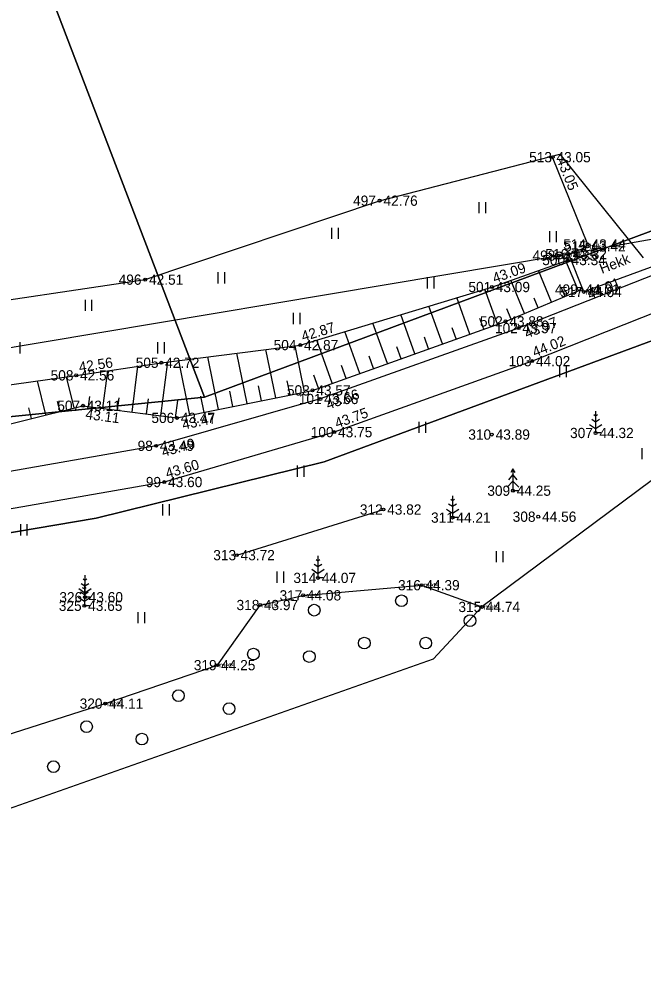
# Model space of a CAD drawing. Extents: x 505800 to 507326, y 6540058 to 6542128.
# Drawn here: x 506203.3 to 506246, y 6540215.6 to 6540280.2 of the extents above; entities that cross this region are included whole.
import ezdxf

# ---------------------------------------------------------------- set-up
doc = ezdxf.new("R2010")
doc.units = 0
for name, color, linetype in [('AED', 7, 'Continuous'), ('HALJASTUS', 7, 'Continuous'), ('KORGUS-EH2000', 7, 'Continuous'), ('MAAMUDEL', 7, 'Continuous'), ('MOOTKORG-EH2000', 7, 'Continuous'), ('MOOTMPUNKT', 7, 'Continuous'), ('MOOTNR', 7, 'Continuous'), ('MOOTPIIR', 7, 'Continuous'), ('MPOHULIIN', 7, 'Continuous'), ('PIIR', 7, 'Continuous'), ('POST', 7, 'Continuous'), ('PUU', 7, 'Continuous'), ('RELJEEF', 7, 'Continuous'), ('TEE', 7, 'Continuous')]:
    doc.layers.add(name, color=color, linetype=linetype)

msp = doc.modelspace()

# ---------------------------------------------------------------- linework, layer by layer
at = {"layer": 'AED'}
msp.add_line((506242.164, 6540264.794), (506239.766, 6540270.763), dxfattribs=at)
at = {"layer": 'HALJASTUS'}
for p, q in [((506234.721, 6540267.693), (506234.721, 6540266.931)), ((506235.176, 6540267.693), (506235.176, 6540266.931)), ((506224.632, 6540265.93), (506224.632, 6540265.169)), ((506225.087, 6540265.93), (506225.087, 6540265.169)), ((506239.555, 6540265.71), (506239.555, 6540264.948)), ((506240.011, 6540265.71), (506240.011, 6540264.948)), ((506216.865, 6540262.885), (506216.865, 6540262.124)), ((506217.32, 6540262.885), (506217.32, 6540262.124)), ((506231.188, 6540262.545), (506231.188, 6540261.784)), ((506231.643, 6540262.545), (506231.643, 6540261.784)), ((506207.776, 6540261.002), (506207.776, 6540260.241)), ((506208.231, 6540261.002), (506208.231, 6540260.241)), ((506222.019, 6540260.101), (506222.019, 6540259.34)), ((506222.474, 6540260.101), (506222.474, 6540259.34)), ((506203.307, 6540258.098), (506203.307, 6540257.337)), ((506212.731, 6540258.098), (506212.731, 6540257.337)), ((506213.186, 6540258.098), (506213.186, 6540257.337)), ((506240.227, 6540256.466), (506240.227, 6540255.705)), ((506240.682, 6540256.466), (506240.682, 6540255.705)), ((506230.618, 6540252.661), (506230.618, 6540251.9)), ((506231.073, 6540252.661), (506231.073, 6540251.9)), ((506245.872, 6540250.858), (506245.872, 6540250.097)), ((506222.291, 6540249.656), (506222.291, 6540248.895)), ((506222.746, 6540249.656), (506222.746, 6540248.895)), ((506213.082, 6540247.012), (506213.082, 6540246.251)), ((506213.537, 6540247.012), (506213.537, 6540246.251)), ((506218.159, 6540243.535), (506228.187, 6540246.655)), ((506203.353, 6540245.65), (506203.353, 6540244.889)), ((506203.808, 6540245.65), (506203.808, 6540244.889)), ((506235.903, 6540243.807), (506235.903, 6540243.046)), ((506236.358, 6540243.807), (506236.358, 6540243.046)), ((506220.889, 6540242.405), (506220.889, 6540241.644)), ((506221.344, 6540242.405), (506221.344, 6540241.644)), ((506211.401, 6540239.641), (506211.401, 6540238.88)), ((506211.856, 6540239.641), (506211.856, 6540238.88))]:
    msp.add_line(p, q, dxfattribs=at)
for points in [[(506298.533, 6540313.056), (506300.788, 6540309.079), (506301.915, 6540305.332), (506301.34, 6540302.125), (506297.996, 6540298.309), (506290.085, 6540289.615), (506283.777, 6540282.658), (506277.199, 6540276.527), (506270.683, 6540272.177), (506261.206, 6540268.283), (506249.615, 6540264.383), (506241.896, 6540261.54), (506240.872, 6540264.129), (506242.157, 6540264.661)], [(506188.596, 6540225.549), (506200.645, 6540230.665), (506209.16, 6540233.376), (506216.83, 6540236.009), (506219.751, 6540240.123), (506222.695, 6540240.784), (506230.801, 6540241.479), (506234.931, 6540239.99)]]:
    msp.add_lwpolyline(points, dxfattribs=at)
for centre in [(506229.424, 6540240.411), (506223.459, 6540239.77), (506234.109, 6540239.049), (506226.882, 6540237.517), (506231.086, 6540237.517), (506219.295, 6540236.765), (506223.118, 6540236.595), (506214.17, 6540233.921), (506217.633, 6540233.03), (506207.884, 6540231.798), (506211.668, 6540230.947), (506205.622, 6540229.064)]:
    msp.add_circle(centre, 0.4, dxfattribs=at)
at = {"layer": 'KORGUS-EH2000'}
for centre in [(506239.766, 6540270.763), (506227.932, 6540267.786), (506242.157, 6540264.661), (506242.164, 6540264.794), (506240.207, 6540264.027), (506240.802, 6540263.724), (506240.872, 6540264.129), (506211.896, 6540262.383), (506235.612, 6540261.879), (506241.741, 6540261.71), (506241.896, 6540261.54), (506236.54, 6540259.529), (506237.432, 6540259.066), (506222.499, 6540257.905), (506212.996, 6540256.696), (506238.366, 6540256.809), (506207.175, 6540255.835), (506223.339, 6540254.808), (506223.872, 6540254.219), (506207.632, 6540253.756), (506214.067, 6540252.925), (506224.827, 6540251.952), (506235.605, 6540251.785), (506242.707, 6540251.893), (506212.634, 6540251.013), (506213.198, 6540248.536), (506237.046, 6540247.944), (506228.187, 6540246.655), (506238.782, 6540246.165), (506232.919, 6540246.101), (506218.159, 6540243.535), (506223.713, 6540241.977), (506230.801, 6540241.479), (506207.77, 6540240.654), (506222.695, 6540240.784), (506207.733, 6540240.071), (506219.751, 6540240.123), (506234.931, 6540239.99), (506216.83, 6540236.009), (506209.16, 6540233.376)]:
    msp.add_circle(centre, 0.1, dxfattribs=at)
at = {"layer": 'MOOTMPUNKT'}
for centre in [(506239.766, 6540270.763), (506227.932, 6540267.786), (506242.157, 6540264.661), (506242.164, 6540264.794), (506240.207, 6540264.027), (506240.802, 6540263.724), (506240.872, 6540264.129), (506211.896, 6540262.383), (506235.612, 6540261.879), (506241.741, 6540261.71), (506241.896, 6540261.54), (506236.54, 6540259.529), (506237.432, 6540259.066), (506222.499, 6540257.905), (506212.996, 6540256.696), (506238.366, 6540256.809), (506207.175, 6540255.835), (506223.339, 6540254.808), (506223.872, 6540254.219), (506207.632, 6540253.756), (506214.067, 6540252.925), (506224.827, 6540251.952), (506235.605, 6540251.785), (506242.707, 6540251.893), (506212.634, 6540251.013), (506213.198, 6540248.536), (506237.046, 6540247.944), (506228.187, 6540246.655), (506238.782, 6540246.165), (506232.919, 6540246.101), (506218.159, 6540243.535), (506223.713, 6540241.977), (506230.801, 6540241.479), (506207.77, 6540240.654), (506222.695, 6540240.784), (506207.733, 6540240.071), (506219.751, 6540240.123), (506234.931, 6540239.99), (506216.83, 6540236.009), (506209.16, 6540233.376)]:
    msp.add_circle(centre, 0.1, dxfattribs=at)
at = {"layer": 'MOOTPIIR'}
for points in [[(506083.03, 6540240.114), (506097.119, 6540244.795), (506135.023, 6540255.311), (506160.43, 6540256.455), (506171.091, 6540256.503), (506184.044, 6540258.184), (506197.806, 6540260.288), (506211.896, 6540262.383), (506227.932, 6540267.786), (506240.253, 6540270.959), (506245.955, 6540263.864)], [(506248.469, 6540250.071), (506234.931, 6540239.99), (506231.591, 6540236.406), (506193.196, 6540222.875), (506188.596, 6540225.549), (506168.901, 6540229.957), (506140.91, 6540229.168), (506108.07, 6540216.496), (506098.399, 6540223.506), (506079.917, 6540216.55)]]:
    msp.add_lwpolyline(points, dxfattribs=at)
at = {"layer": 'MPOHULIIN'}
msp.add_lwpolyline([(506112.189, 6540233.927), (506153.828, 6540249.522), (506196.936, 6540256.778), (506240.207, 6540264.027), (506283.784, 6540271.755), (506305.802, 6540315.044)], dxfattribs=at)
at = {"layer": 'PIIR'}
for points in [[(506190.15, 6540321.81), (506202.45, 6540325.81), (506206.43, 6540327.67), (506257.9, 6540343.01), (506275.56, 6540347.96), (506281.36, 6540349.61), (506282.62, 6540347.28), (506304.35, 6540308.95), (506274.54, 6540277.85), (506268.55, 6540273.9), (506215.95, 6540254.34)], [(506133.36, 6540278.52), (506190.15, 6540321.81), (506215.95, 6540254.34), (506141.06, 6540246.81)]]:
    msp.add_lwpolyline(points, close=True, dxfattribs=at)
for points in [[(506272.39, 6540267.75), (506224.13, 6540249.92), (506208.53, 6540246.07), (506198.96, 6540244.45), (506187, 6540243.59), (506158.97, 6540240.95), (506142.88, 6540238.84), (506141.06, 6540246.81), (506215.95, 6540254.34), (506268.55, 6540273.9)], [(506028.99, 6540136.11), (506018.19, 6540200.68), (506049.36, 6540212.6), (506053.99, 6540200.79), (506052.51, 6540200.31), (506055.45, 6540190.69), (506062.61, 6540193.04), (506059.62, 6540202.68), (506057.79, 6540202.01), (506053.1, 6540214.07), (506081.75, 6540225.93), (506090.32, 6540182.64), (506150.17, 6540208.02), (506142.88, 6540238.84), (506158.97, 6540240.95), (506187, 6540243.59), (506198.96, 6540244.45), (506208.53, 6540246.07), (506224.13, 6540249.92), (506272.39, 6540267.75)]]:
    msp.add_lwpolyline(points, dxfattribs=at)
at = {"layer": 'POST'}
msp.add_circle((506240.207, 6540264.027), 0.25, dxfattribs=at)
at = {"layer": 'PUU'}
for p, q in [((506242.707, 6540253.393), (506242.707, 6540251.893)), ((506242.707, 6540252.643), (506242.44, 6540252.821)), ((506242.707, 6540253.043), (506242.582, 6540253.126)), ((506242.831, 6540253.126), (506242.707, 6540253.043)), ((506242.973, 6540252.821), (506242.707, 6540252.643)), ((506242.282, 6540252.482), (506242.707, 6540252.2)), ((506242.707, 6540252.2), (506243.131, 6540252.482)), ((506243.067, 6540251.893), (506242.707, 6540251.893)), ((506237.046, 6540249.444), (506236.896, 6540249.194)), ((506237.196, 6540249.194), (506237.046, 6540249.444)), ((506237.046, 6540249.444), (506237.046, 6540247.944)), ((506237.046, 6540249.044), (506236.746, 6540248.694)), ((506237.346, 6540248.694), (506237.046, 6540249.044)), ((506237.046, 6540248.594), (506236.646, 6540248.194)), ((506237.446, 6540248.194), (506237.046, 6540248.594)), ((506232.919, 6540247.601), (506232.919, 6540246.101)), ((506237.406, 6540247.944), (506237.046, 6540247.944)), ((506232.919, 6540246.851), (506232.652, 6540247.028)), ((506232.919, 6540247.251), (506232.794, 6540247.334)), ((506233.043, 6540247.334), (506232.919, 6540247.251)), ((506233.185, 6540247.028), (506232.919, 6540246.851)), ((506232.495, 6540246.69), (506232.919, 6540246.407)), ((506232.919, 6540246.407), (506233.343, 6540246.69)), ((506233.279, 6540246.101), (506232.919, 6540246.101)), ((506223.713, 6540243.127), (506223.589, 6540243.21)), ((506223.713, 6540243.477), (506223.713, 6540241.977)), ((506223.838, 6540243.21), (506223.713, 6540243.127)), ((506223.289, 6540242.567), (506223.713, 6540242.284)), ((506223.713, 6540242.727), (506223.447, 6540242.905)), ((506223.98, 6540242.905), (506223.713, 6540242.727)), ((506223.713, 6540242.284), (506224.138, 6540242.567)), ((506207.77, 6540241.804), (506207.646, 6540241.886)), ((506207.77, 6540242.154), (506207.77, 6540240.654)), ((506207.895, 6540241.886), (506207.77, 6540241.804)), ((506224.073, 6540241.977), (506223.713, 6540241.977)), ((506207.346, 6540241.243), (506207.77, 6540240.96)), ((506207.77, 6540241.404), (506207.504, 6540241.581)), ((506207.733, 6540241.221), (506207.609, 6540241.304)), ((506207.733, 6540241.571), (506207.733, 6540240.071)), ((506207.858, 6540241.304), (506207.733, 6540241.221)), ((506208.037, 6540241.581), (506207.77, 6540241.404)), ((506207.77, 6540240.96), (506208.194, 6540241.243)), ((506207.309, 6540240.66), (506207.733, 6540240.378)), ((506207.733, 6540240.821), (506207.467, 6540240.999)), ((506208, 6540240.999), (506207.733, 6540240.821)), ((506207.733, 6540240.378), (506208.158, 6540240.66)), ((506208.13, 6540240.654), (506207.77, 6540240.654)), ((506208.093, 6540240.071), (506207.733, 6540240.071))]:
    msp.add_line(p, q, dxfattribs=at)
at = {"layer": 'RELJEEF'}
for p, q in [((506241.536, 6540261.624), (506240.674, 6540263.679)), ((506239.691, 6540260.85), (506238.787, 6540263.008)), ((506235.991, 6540259.333), (506235.133, 6540261.734)), ((506237.847, 6540260.077), (506236.9, 6540262.337)), ((506240.614, 6540261.237), (506240.349, 6540261.869)), ((506234.108, 6540258.659), (506233.216, 6540261.153)), ((506238.769, 6540260.464), (506238.491, 6540261.126)), ((506232.225, 6540257.986), (506231.3, 6540260.572)), ((506230.342, 6540257.312), (506229.384, 6540259.991)), ((506236.925, 6540259.69), (506236.634, 6540260.384)), ((506228.458, 6540256.639), (506227.467, 6540259.411)), ((506235.05, 6540258.996), (506234.787, 6540259.73)), ((506226.575, 6540255.965), (506225.551, 6540258.83)), ((506233.166, 6540258.323), (506232.894, 6540259.085)), ((506222.787, 6540254.696), (506222.145, 6540257.86)), ((506224.692, 6540255.292), (506223.635, 6540258.249)), ((506231.283, 6540257.649), (506231.001, 6540258.439)), ((506218.867, 6540253.9), (506218.166, 6540257.353)), ((506220.827, 6540254.298), (506220.155, 6540257.607)), ((506229.4, 6540256.976), (506229.108, 6540257.793)), ((506212.974, 6540253.066), (506213.451, 6540256.754)), ((506214.947, 6540253.104), (506214.187, 6540256.847)), ((506216.907, 6540253.502), (506216.177, 6540257.1)), ((506227.517, 6540256.302), (506227.215, 6540257.148)), ((506209.007, 6540253.579), (506209.34, 6540256.155)), ((506210.991, 6540253.322), (506211.396, 6540256.459)), ((506225.634, 6540255.629), (506225.321, 6540256.502)), ((506205.095, 6540253.129), (506204.517, 6540255.465)), ((506207.037, 6540253.609), (506206.509, 6540255.742)), ((506221.807, 6540254.497), (506221.61, 6540255.468)), ((506223.751, 6540254.955), (506223.428, 6540255.856)), ((506217.887, 6540253.701), (506217.673, 6540254.759)), ((506219.847, 6540254.099), (506219.641, 6540255.113)), ((506206.066, 6540253.369), (506205.9, 6540254.039)), ((506208.016, 6540253.707), (506208.105, 6540254.396)), ((506209.999, 6540253.45), (506210.11, 6540254.307)), ((506211.983, 6540253.194), (506212.115, 6540254.219)), ((506213.966, 6540252.938), (506214.119, 6540254.122)), ((506215.927, 6540253.303), (506215.704, 6540254.404)), ((506204.125, 6540252.889), (506203.944, 6540253.62))]:
    msp.add_line(p, q, dxfattribs=at)
for points in [[(506186.229, 6540254.552), (506197.842, 6540254.535), (506207.175, 6540255.835), (506212.996, 6540256.696), (506222.499, 6540257.905), (506235.612, 6540261.879), (506240.802, 6540263.724)], [(506187.313, 6540250.618), (506199.797, 6540251.818), (506207.632, 6540253.756), (506214.067, 6540252.925), (506223.339, 6540254.808), (506236.54, 6540259.529), (506241.741, 6540261.71)]]:
    msp.add_lwpolyline(points, dxfattribs=at)
at = {"layer": 'TEE'}
for points in [[(506250.031, 6540264.042), (506237.432, 6540259.066), (506223.872, 6540254.219), (506212.634, 6540251.013), (506200.022, 6540248.8), (506187.383, 6540247.629), (506174.426, 6540246.673), (506168.123, 6540246.063), (506162.988, 6540245.422), (506156.937, 6540244.719), (506147.401, 6540244.066), (506139.254, 6540244.367), (506135.743, 6540244.402), (506126.133, 6540243.916), (506116.327, 6540241.664), (506104.313, 6540238.326), (506099.073, 6540236.742), (506091.024, 6540234.378), (506084.768, 6540232.16)], [(506250.904, 6540261.782), (506238.366, 6540256.809), (506224.827, 6540251.952), (506213.198, 6540248.536), (506200.494, 6540246.321), (506187.779, 6540245.271), (506174.602, 6540244.231), (506168.346, 6540243.484), (506163.12, 6540242.933), (506157.471, 6540242.007), (506148.214, 6540239.664), (506142.677, 6540239.46), (506137.814, 6540240.039)]]:
    msp.add_lwpolyline(points, dxfattribs=at)

# ---------------------------------------------------------------- texts
at = {"layer": 'HALJASTUS'}
msp.add_text('Hekk', height=0.7, rotation=21.06856, dxfattribs=at).set_placement((506243.135, 6540262.775))
at = {"layer": 'KORGUS-EH2000'}
for s, rotation, p in [(' 43.05', 291.88791, (506239.928, 6540270.828)), (' 43.09', 19.57223, (506235.553, 6540262.044)), (' 44.01', 22.74412, (506242.08, 6540260.903)), (' 43.97', 21.5507, (506237.753, 6540258.253)), (' 42.87', 16.86057, (506222.448, 6540258.072)), (' 44.02', 21.63789, (506238.301, 6540256.971)), (' 42.56', 8.41099, (506207.149, 6540256.008)), (' 43.66', 19.67109, (506224.166, 6540253.395)), (' 43.11', 352.63708, (506207.52, 6540252.889)), (' 43.75', 19.73504, (506224.768, 6540252.117)), (' 43.47', 11.48011, (506214.241, 6540252.067)), (' 43.49', 15.9231, (506212.874, 6540250.172)), (' 43.60', 16.37079, (506213.149, 6540248.704))]:
    msp.add_text(s, height=0.7, rotation=rotation, dxfattribs=at).set_placement(p)
for s, p in [(' 42.76', (506227.932, 6540267.436)), (' 43.42', (506242.157, 6540264.311)), (' 42.51', (506211.896, 6540262.033)), (' 43.89', (506235.605, 6540251.435)), (' 43.82', (506228.187, 6540246.305)), (' 44.56', (506238.782, 6540245.815)), (' 43.72', (506218.159, 6540243.185)), (' 44.39', (506230.801, 6540241.129)), (' 43.65', (506207.733, 6540239.721)), (' 43.97', (506219.751, 6540239.772)), (' 44.74', (506234.931, 6540239.64)), (' 44.25', (506216.83, 6540235.659)), (' 44.11', (506209.16, 6540233.026))]:
    msp.add_text(s, height=0.7, dxfattribs=at).set_placement(p)
at = {"layer": 'MAAMUDEL'}
for s, p in [(' hek', (506240.872, 6540263.954)), (' hek', (506242.157, 6540264.486)), (' hek', (506241.896, 6540261.365)), (' mets', (506230.801, 6540241.304)), (' mets', (506222.695, 6540240.609)), (' mets', (506219.751, 6540239.947)), (' mets', (506234.931, 6540239.815)), (' mets', (506216.83, 6540235.834)), (' mets', (506209.16, 6540233.201))]:
    msp.add_text(s, height=0.35, dxfattribs=at).set_placement(p)
at = {"layer": 'MOOTKORG-EH2000'}
for s, p in [(' 43.05', (506239.766, 6540270.413)), (' 42.76', (506227.932, 6540267.436)), (' 43.42', (506242.157, 6540264.311)), (' 43.44', (506242.164, 6540264.444)), (' 43.35', (506240.207, 6540263.677)), (' 43.32', (506240.872, 6540263.779)), (' 43.34', (506240.802, 6540263.374)), (' 42.51', (506211.896, 6540262.033)), (' 43.09', (506235.612, 6540261.529)), (' 44.01', (506241.741, 6540261.36)), (' 44.04', (506241.896, 6540261.19)), (' 43.88', (506236.54, 6540259.179)), (' 43.97', (506237.432, 6540258.717)), (' 42.87', (506222.499, 6540257.555)), (' 42.72', (506212.996, 6540256.346)), (' 44.02', (506238.366, 6540256.459)), (' 42.56', (506207.175, 6540255.485)), (' 43.57', (506223.339, 6540254.458)), (' 43.11', (506207.632, 6540253.406)), (' 43.66', (506223.872, 6540253.869)), (' 43.47', (506214.067, 6540252.575)), (' 43.75', (506224.827, 6540251.602)), (' 43.89', (506235.605, 6540251.435)), (' 44.32', (506242.707, 6540251.543)), (' 43.49', (506212.634, 6540250.663)), (' 43.60', (506213.198, 6540248.186)), (' 44.25', (506237.046, 6540247.594)), (' 43.82', (506228.187, 6540246.305)), (' 44.21', (506232.919, 6540245.751)), (' 44.56', (506238.782, 6540245.815)), (' 43.72', (506218.159, 6540243.185)), (' 44.07', (506223.713, 6540241.627)), (' 44.39', (506230.801, 6540241.129)), (' 44.08', (506222.695, 6540240.434)), (' 43.65', (506207.733, 6540239.721)), (' 43.60', (506207.77, 6540240.304)), (' 43.97', (506219.751, 6540239.772)), (' 44.74', (506234.931, 6540239.64)), (' 44.25', (506216.83, 6540235.659)), (' 44.11', (506209.16, 6540233.026))]:
    msp.add_text(s, height=0.7, dxfattribs=at).set_placement(p)
at = {"layer": 'MOOTNR'}
for s, p in [('513 ', (506238.156, 6540270.413)), ('497 ', (506226.113, 6540267.436)), ('514 ', (506240.484, 6540264.444)), ('515 ', (506240.547, 6540264.311)), ('498 ', (506238.388, 6540263.677)), ('516 ', (506239.262, 6540263.779)), ('500 ', (506239.052, 6540263.374)), ('496 ', (506210.076, 6540262.033)), ('501 ', (506234.002, 6540261.529)), ('499 ', (506239.922, 6540261.36)), ('517 ', (506240.286, 6540261.19)), ('502 ', (506234.79, 6540259.179)), ('102 ', (506235.822, 6540258.717)), ('504 ', (506220.679, 6540257.555)), ('505 ', (506211.246, 6540256.346)), ('103 ', (506236.756, 6540256.459)), ('508 ', (506205.425, 6540255.485)), ('503 ', (506221.589, 6540254.458)), ('507 ', (506205.882, 6540253.406)), ('101 ', (506222.402, 6540253.869)), ('506 ', (506212.317, 6540252.575)), ('100 ', (506223.217, 6540251.602)), ('310 ', (506233.995, 6540251.435)), ('307 ', (506240.957, 6540251.543)), ('98 ', (506211.374, 6540250.663)), ('99 ', (506211.939, 6540248.186)), ('309 ', (506235.296, 6540247.594)), ('312 ', (506226.577, 6540246.305)), ('311 ', (506231.449, 6540245.751)), ('308 ', (506237.032, 6540245.815)), ('313 ', (506216.549, 6540243.185)), ('314 ', (506222.033, 6540241.627)), ('316 ', (506229.191, 6540241.129)), ('317 ', (506221.085, 6540240.434)), ('325 ', (506205.983, 6540239.721)), ('326 ', (506206.02, 6540240.304)), ('318 ', (506218.141, 6540239.772)), ('315 ', (506233.321, 6540239.64)), ('319 ', (506215.22, 6540235.659)), ('320 ', (506207.41, 6540233.026))]:
    msp.add_text(s, height=0.7, dxfattribs=at).set_placement(p)

doc.saveas('drawing.dxf')
